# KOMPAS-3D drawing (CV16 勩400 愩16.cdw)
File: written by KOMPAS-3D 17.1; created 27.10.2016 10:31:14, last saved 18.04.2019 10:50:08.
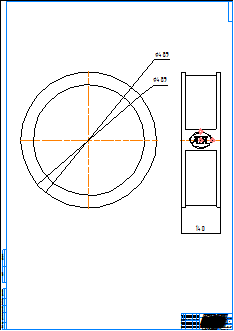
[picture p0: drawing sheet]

Sheet 1: A0, portrait

Title block, sheet 1: name: CV16 Ду400 Ру16; material: Внимание! Данный продукт является объектом авторского права ООО «Торговый Дом АДЛ». / Запрещается изменение, копирование, распространение / (в том числе путем копирования на другие сайты и ресурсы в Интернете) / или любое иное использование информации и объектов без предварительного / согласия правообладателя (ООО «Торговый Дом АДЛ»).; mass: 280,8; sheets: 1; organisation: ООО "Торговый дом АДЛ"; sheet format: A0; stored path: \\adlc.lan\data\АДЛ_ПКД\3D-модели\ADL production\Клапаны обратные ГРАНЛОК\CV16\KOMPAS 2D\CV16 Ду400 Ру16.cdw

Views: Вид 1, Проекционный вид 2
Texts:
  Klimkovich
  ADL
Dimensions and other numbers on the sheet: 489; 140; 1:1; 1; 280,8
